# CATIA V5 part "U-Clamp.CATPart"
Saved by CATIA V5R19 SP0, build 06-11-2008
Part number: U-Clamp
Bounding box of the stored display mesh (mm): x -23 to 23, y -6.5 to 6.5, z -25 to 29
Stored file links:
  C:\Users\CADCIM\Desktop\CAT19\c13\Excercise-1\Part & Asm files\U-Clamp.CATPart
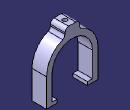
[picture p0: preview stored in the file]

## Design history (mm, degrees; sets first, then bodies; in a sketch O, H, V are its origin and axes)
Body1 (main body)
  Sketch1 on zx-plane, origin (0, 0, 0), H (-1, 0, 0), V (0, 0, 1)
    arc A1 centre (0, 0) radius 18 from (18, 0) to (-18, 0) ccw
    point P1 (-18, 0)
    point P2 (18, 0)
    line L1 (-18, 0) -> (-18, -22)
    point P3 (-18, -22)
    line L2 (-18, -22) -> (-13.5, -22)
    point P4 (-13.5, -22)
    line L3 (-13.5, -22) -> (-13.5, -25)
    point P5 (-13.5, -25)
    line L4 (-13.5, -25) -> (-23, -25)
    point P6 (-23, -25)
    line L5 (-23, -25) -> (-23, 0)
    point P7 (-23, 0)
    arc A2 centre (0, 0) radius 23 from (-23, 0) to (-6.5, 22.0624) cw
    point P9 (23, 0)
    point P10 (23, 0)
    point P11 (23, -25)
    line L6 (23, -25) -> (23, 0)
    point P12 (13.5, -25)
    line L7 (13.5, -25) -> (23, -25)
    point P13 (13.5, -22)
    line L8 (13.5, -22) -> (13.5, -25)
    point P14 (18, -22)
    line L9 (18, -22) -> (13.5, -22)
    point P15 (18, 0)
    line L10 (18, 0) -> (18, -22)
    line L11 (-6.5, 22.0624) -> (-6.5, 29)
    point P16 (-6.5, 29)
    line L12 (-6.5, 29) -> (6.5, 29)
    point P17 (6.5, 29)
    line L13 (6.5, 29) -> (6.5, 22.0624)
    point P18 (6.5, 22.0624)
    arc A3 centre (0, 0) radius 23 from (6.5, 22.0624) to (23, 0) cw
    distance L3 V = 13.5
    distance H L4 = 25
    distance V L5 = 23
    distance P16 P17 = 13
    distance L11 V = 6.5
    distance L7 L12 = 54
    distance L1 L5 = 5
    length L3 = 3
    coincidence: P1 H, P2 H, P7 H, A2 P18, A2 A3, P2 P15, P9 P10
    tangency: L1 A1, A2 L5
    horizontal: L2 H, L4 H, L12 H
    vertical: L3 V, L5 V, L11 V, L13 V
    concentricity: A2 A1
    symmetry: P7 P10 V, P6 P11 V, L5 L6 V, P5 P12 V, L4 L7 V, P4 P13 V, L3 L8 V, P3 P14 V, L2 L9 V, P1 P15 V, L1 L10 V
  Pad1: profile Sketch1, direction (0, -1, 0), length 6.5, mirrored extent
  Fillet1: radius 3.302, on 4 edges
  Sketch2 on face of Pad1, origin (-0.057, 2.6412, 29), H (1, 0, 0), V (0, 1, 0)
    point P1 (0.057, -2.6412)
    reference intersected line E1 through (0.057, 0) direction (0, 1) from yz-plane
    reference intersected line E2 through (0, -2.6412) direction (-1, 0) from zx-plane
    coincidence: E1 P1, E2 P1
  Hole1: placed by Sketch2, at (0, 0, 29) direction (0, 0, -1), diameter 4, depth 25.4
